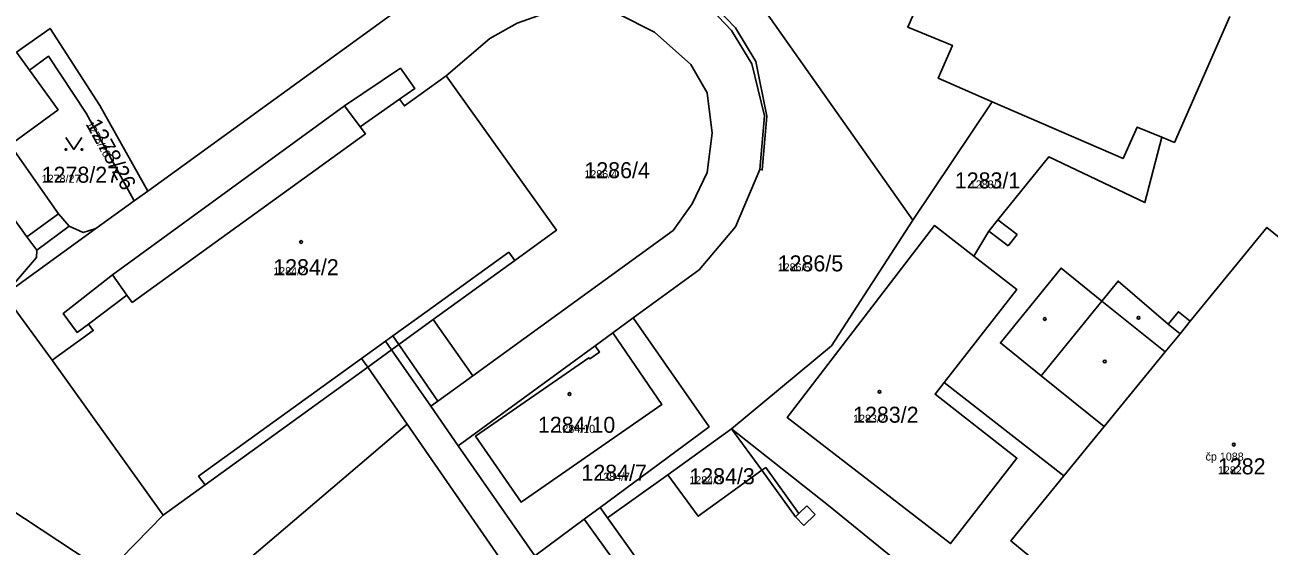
# Model space of a CAD drawing. Extents: x -763628 to -761565, y -976033 to -973833.
# Drawn here: x -762052.9 to -761897.5, y -975375.2 to -975310.1 of the extents above; entities that cross this region are included whole.
import ezdxf

# ---------------------------------------------------------------- set-up
doc = ezdxf.new("R2010")
doc.units = 0
for name, color, linetype in [('KN_cisla parcel 1000', 7, 'Continuous'), ('KN_cisla parcel 500', 7, 'Continuous'), ('KN_cisla popisna 500', 7, 'Continuous'), ('KN_hranice parcel', 7, 'Continuous'), ('KN_vnitrni kresba parcel', 7, 'Continuous'), ('KN_znacky budov', 7, 'Continuous'), ('KN_znacky kultur', 7, 'Continuous')]:
    doc.layers.add(name, color=color, linetype=linetype)

msp = doc.modelspace()

# ---------------------------------------------------------------- linework, layer by layer
at = {"layer": 'KN_hranice parcel'}
for p, q in [((-762052.32, -975315.72), (-762053.95, -975313.47)), ((-761932.06, -975319.66), (-761941.96, -975334.44)), ((-762039.26, -975332.05), (-762037.56, -975330.82)), ((-762044.03, -975335.52), (-762039.26, -975332.05)), ((-762055.44, -975343.79), (-762044.03, -975335.52)), ((-762054.22, -975345.47), (-762049.51, -975351.97)), ((-761976.89, -975346.68), (-761979.44, -975348.54)), ((-761981.66, -975350.16), (-761979.44, -975348.54)), ((-761981.66, -975350.16), (-761998.75, -975362.64)), ((-762049.51, -975351.97), (-762035.62, -975371.33)), ((-761938.05, -975354.75), (-761923.08, -975366.4)), ((-762005.14, -975359.95), (-761991.74, -975379.28)), ((-761964.64, -975360.55), (-761972.58, -975366.3)), ((-761989.17, -975376.4), (-761998.75, -975362.64)), ((-761972.58, -975366.3), (-761980.11, -975371.67)), ((-762035.62, -975371.33), (-762042.65, -975378.51))]:
    msp.add_line(p, q, dxfattribs=at)
for points in [[(-761915.35, -975288.36), (-761919.1, -975298.17), (-761917.28, -975298.95), (-761918.57, -975301.82), (-761935.62, -975294.41), (-761942.59, -975310.35), (-761937.01, -975312.62), (-761938.79, -975316.73), (-761932.06, -975319.66)], [(-762006.43, -975296.49), (-762003.52, -975298.03), (-762002.09, -975299.4), (-762001.34, -975302.33), (-762003.18, -975305.88), (-762037.56, -975330.82)], [(-761976.89, -975346.68), (-761968.67, -975340.68), (-761964.13, -975335.31), (-761961.07, -975328.15), (-761960.77, -975328.18), (-761960.2, -975321.45), (-761961.56, -975314.63), (-761964.12, -975310.44), (-761967.67, -975306.73), (-761972.46, -975304.19), (-761975.86, -975302.74)], [(-761941.96, -975334.44), (-761963.24, -975304.25), (-761966.26, -975303.92)], [(-762000.28, -975316.42), (-761994.83, -975311.78), (-761991.39, -975309.85), (-761986.68, -975308.17), (-761978.76, -975308.66), (-761974.24, -975310.97), (-761969.69, -975314.99), (-761967.66, -975318.56), (-761967.04, -975323.6), (-761967.67, -975328.52), (-761969.54, -975332.44), (-761971.92, -975335.76), (-761996.94, -975353.91)], [(-762037.56, -975330.82), (-762043.55, -975320.14), (-762049.76, -975310.51), (-762053.95, -975313.47)], [(-762052.32, -975315.72), (-762049.93, -975313.98), (-762045.25, -975321.1), (-762039.26, -975332.05)], [(-762044.03, -975335.52), (-762045.63, -975336.01), (-762047.36, -975335.23), (-762048.71, -975333.66), (-762054.72, -975325.04), (-762048.75, -975320.67), (-762052.32, -975315.72)], [(-762000.28, -975316.42), (-762005.49, -975320.18), (-762006.1, -975319.35), (-762004.2, -975318.02), (-762005.99, -975315.47), (-762012.95, -975320.19), (-762041.97, -975341.31), (-762048.1, -975346.12), (-762046.39, -975348.49), (-762044.94, -975347.44), (-762044.35, -975348.25), (-762049.51, -975351.97)], [(-761996.94, -975353.91), (-762001.9, -975346.88), (-761991.67, -975339.48), (-761986.5, -975335.72), (-762000.28, -975316.42)], [(-761932.06, -975319.66), (-761915.7, -975326.76), (-761913.93, -975322.84), (-761910.84, -975324.11), (-761912.97, -975332.27), (-761924.96, -975326.54), (-761931.33, -975334.42), (-761932.45, -975335.84), (-761934.35, -975338.96)], [(-762122.62, -975350.65), (-762114.56, -975345.63), (-762103.85, -975360.52), (-762058.92, -975327.9), (-762052.67, -975336.54), (-762051.39, -975338.23), (-762051.47, -975339.13), (-762055.44, -975343.79)], [(-761941.96, -975334.44), (-761952.12, -975350.15), (-761964.64, -975360.55)], [(-761938.05, -975354.75), (-761939.18, -975356.21), (-761928.96, -975364.19), (-761937.25, -975374.87), (-761957.68, -975359.11), (-761939.27, -975335.13), (-761934.35, -975338.96)], [(-761923.08, -975366.4), (-761918.06, -975360.26), (-761925.95, -975353.93), (-761931.03, -975349.8), (-761923.45, -975340.45), (-761918.36, -975344.59), (-761916.32, -975342.08), (-761910.05, -975347.45), (-761908.79, -975345.9), (-761907.31, -975347.1), (-761897.73, -975335.37), (-761892.24, -975339.84)], [(-761934.35, -975338.96), (-761928.99, -975343.12), (-761938.05, -975354.75)], [(-761980.11, -975371.67), (-761981.04, -975370.37), (-761967.41, -975360.27), (-761976.89, -975346.68)], [(-761979.44, -975348.54), (-761973.32, -975357.48), (-761990.91, -975369.68), (-761996.59, -975361.47), (-761982.43, -975351.65), (-761982.33, -975351.79), (-761981.11, -975350.95), (-761981.66, -975350.16)], [(-762035.62, -975371.33), (-762030.39, -975367.54), (-762010.07, -975352.81), (-762005.14, -975359.95)], [(-761998.75, -975362.64), (-762002.18, -975357.71), (-762001.32, -975357.09), (-761996.94, -975353.91)], [(-762005.14, -975359.95), (-762029.61, -975380.8), (-762028.7, -975390.83), (-762020.76, -975394.85), (-762019.58, -975395.45), (-761998.82, -975383.39)], [(-761964.64, -975360.55), (-761960.81, -975365.72), (-761968.78, -975371.46), (-761972.58, -975366.3)], [(-761964.64, -975360.55), (-761952.49, -975370.12), (-761909.88, -975404.75)], [(-762042.65, -975378.51), (-762059.11, -975367.68), (-762082.22, -975400.57)], [(-761923.08, -975366.4), (-761929.72, -975374.53), (-761924.25, -975379.02), (-761924.35, -975379.14), (-761917.82, -975384.5), (-761919.08, -975386.03), (-761917.7, -975387.16), (-761916.15, -975388.44), (-761913.61, -975390.52), (-761912.25, -975388.88), (-761906.45, -975393.64), (-761902.69, -975396.75)], [(-761989.17, -975376.4), (-761983.01, -975371.83), (-761976.2, -975381.33)], [(-761980.11, -975371.67), (-761974.21, -975379.94), (-761976.2, -975381.33)]]:
    msp.add_lwpolyline(points, dxfattribs=at)
at = {"layer": 'KN_vnitrni kresba parcel'}
for p, q in [((-761967.95, -975307.26), (-761964.63, -975310.75)), ((-761902.34, -975309), (-761909.27, -975324.75)), ((-761964.63, -975310.75), (-761962.07, -975314.94)), ((-761962.07, -975314.94), (-761960.5, -975321.42)), ((-762011.01, -975322.79), (-762006.1, -975319.35)), ((-762012.95, -975320.19), (-762011.01, -975322.79)), ((-761960.5, -975321.42), (-761961.07, -975328.15)), ((-762039.5, -975344.74), (-762010.35, -975323.69)), ((-762010.35, -975323.69), (-762011.01, -975322.79)), ((-761909.27, -975324.75), (-761910.84, -975324.11)), ((-762048.71, -975333.66), (-762052.67, -975336.54)), ((-761931.33, -975334.42), (-761928.93, -975336.24)), ((-762047.36, -975335.23), (-762051.39, -975338.23)), ((-761932.45, -975335.84), (-761930.05, -975337.66)), ((-761928.93, -975336.24), (-761930.05, -975337.66)), ((-761992.43, -975338.44), (-762002.66, -975345.83)), ((-761992.43, -975338.44), (-761991.67, -975339.48)), ((-762040.16, -975343.82), (-762041.97, -975341.31)), ((-762044.94, -975347.44), (-762040.16, -975343.82)), ((-762040.16, -975343.82), (-762039.5, -975344.74)), ((-762006.92, -975348.92), (-762002.66, -975345.83)), ((-761925.95, -975353.93), (-761918.36, -975344.59)), ((-761918.36, -975344.59), (-761910.44, -975350.92)), ((-762001.9, -975346.88), (-762006.18, -975349.99)), ((-761910.05, -975347.45), (-761908.58, -975348.65)), ((-761908.58, -975348.65), (-761907.31, -975347.1)), ((-762007.84, -975349.58), (-762006.92, -975348.92)), ((-762006.18, -975349.99), (-762006.92, -975348.92)), ((-761910.44, -975350.92), (-761908.58, -975348.65)), ((-762007.84, -975349.58), (-762010.83, -975351.75)), ((-762007.09, -975350.65), (-762007.84, -975349.58)), ((-762006.18, -975349.99), (-762007.09, -975350.65)), ((-762001.32, -975357.09), (-762006.18, -975349.99)), ((-762010.83, -975351.75), (-762031.19, -975366.43)), ((-762010.83, -975351.75), (-762010.07, -975352.81)), ((-762007.09, -975350.65), (-762010.07, -975352.81)), ((-762002.18, -975357.71), (-762007.09, -975350.65)), ((-761910.44, -975350.92), (-761918.06, -975360.26)), ((-761960.81, -975365.72), (-761960.33, -975365.37)), ((-761956.63, -975371.52), (-761960.81, -975365.72)), ((-761960.33, -975365.37), (-761956.2, -975371.11)), ((-762031.19, -975366.43), (-762030.39, -975367.54)), ((-761983.01, -975371.83), (-761981.04, -975370.37)), ((-761956.2, -975371.11), (-761955.19, -975370.15)), ((-761955.19, -975370.15), (-761954.16, -975371.24)), ((-761956.63, -975371.52), (-761956.2, -975371.11)), ((-761955.6, -975372.6), (-761956.63, -975371.52)), ((-761954.16, -975371.24), (-761955.6, -975372.6))]:
    msp.add_line(p, q, dxfattribs=at)
at = {"layer": 'KN_znacky budov'}
for centre in [(-762018.4, -975337.19), (-761925.48, -975346.81), (-761913.76, -975346.66), (-761917.99, -975352.12), (-761984.85, -975356.19), (-761946.13, -975355.9), (-761901.87, -975362.51)]:
    msp.add_circle(centre, 0.175, dxfattribs=at)
at = {"layer": 'KN_znacky kultur'}
msp.add_lwpolyline([(-762047.78, -975324.13), (-762046.78, -975325.63), (-762045.78, -975324.13)], dxfattribs=at)
for centre in [(-762047.78, -975325.63), (-762045.78, -975325.63)]:
    msp.add_circle(centre, 0.1, dxfattribs=at)

# ---------------------------------------------------------------- texts
at = {"layer": 'KN_cisla parcel 1000'}
msp.add_text('1278/26', height=2, rotation=299, dxfattribs=at).set_placement((-762045.34, -975322.47))
for s, p in [('1286/4', (-761983, -975329.22)), ('1278/27', (-762050.8, -975329.78)), ('1283/1', (-761936.72, -975330.49)), ('1284/2', (-762021.87, -975341.34)), ('1286/5', (-761958.85, -975340.86)), ('1283/2', (-761949.43, -975359.77)), ('1284/10', (-761988.81, -975361.03)), ('1282', (-761903.85, -975366.22)), ('1284/7', (-761983.37, -975367.02)), ('1284/3', (-761969.89, -975367.46))]:
    msp.add_text(s, height=2, dxfattribs=at).set_placement(p)
at = {"layer": 'KN_cisla parcel 500'}
msp.add_text('1278/26', height=1, rotation=299, dxfattribs=at).set_placement((-762045.34, -975322.47))
for s, p in [('1278/27', (-762050.8, -975329.78)), ('1286/4', (-761983, -975329.22)), ('1283/1', (-761934.84, -975330.49)), ('1284/2', (-762021.87, -975341.34)), ('1286/5', (-761958.85, -975340.86)), ('1283/2', (-761949.43, -975359.77)), ('1284/10', (-761986.49, -975361.03)), ('1284/7', (-761981.39, -975367.02)), ('1282', (-761903.85, -975366.22)), ('1284/3', (-761969.89, -975367.46))]:
    msp.add_text(s, height=1, dxfattribs=at).set_placement(p)
at = {"layer": 'KN_cisla popisna 500'}
msp.add_text('čp 1088', height=1, dxfattribs=at).set_placement((-761905.39, -975364.5))

doc.saveas('drawing.dxf')
